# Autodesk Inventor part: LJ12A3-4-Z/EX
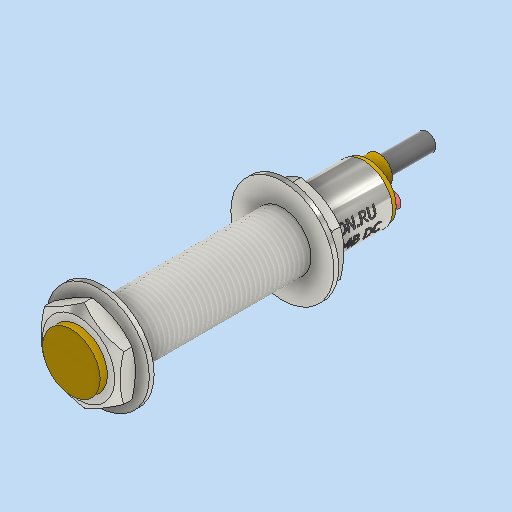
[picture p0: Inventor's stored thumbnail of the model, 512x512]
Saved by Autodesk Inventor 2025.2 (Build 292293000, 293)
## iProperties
Created: 2026-04
Part Number: LJ12A3-4-Z/EX
Material: Типовые
Description: D290-00327
Document SubType Name: Modeling
Designer: DN.RU
Mass: 50 g
Surface Area: 41.1858 cm^2
Volume: 8.64663 cm^3
Density: 5.78253 g/cm^3
Appearance: По умолчанию
Title: Концевой выключатель DN.ru
Author: DN.RU
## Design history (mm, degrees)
sketch "Эскиз1"
  geometry: C1 r 6 at (0, 0); 1 further point
  constraints: 1 centre point, 1 coincident
  dimensions: "d0" = 12 diameter of C1
extrude "Выдавливание1" new body sketch "Эскиз1" distance "d1" = 0.5; taper "d2" = 0 deg
sketch "Эскиз2"
  geometry: C1 r 6 at (0, 0); 1 further point
  constraints: 1 centre point, 1 coincident
  dimensions: "d3" = 12 diameter of C1
extrude "Выдавливание2" join sketch "Эскиз2" distance "d4" = 1; taper "d5" = 0 deg
sketch "Эскиз3"
  geometry: L1 (0, 0)-(8.25, 0); L2 (8.25, -4.763)-(0, -9.526); L3 (0, -9.526)-(-8.25, -4.763); L4 (-8.25, -4.763)-(-8.25, 4.763); L5 (-8.25, 4.763)-(0, 9.526); L6 (0, 9.526)-(8.25, 4.763); L7 (8.25, 4.763)-(8.25, -4.763); 1 further point
  constraints: 14 end point, 1 coincident, 1 horizontal, 1 midpoint, 13 other
  dimensions: "d6" = 8.25 distance of L1.start L1.end
extrude "Выдавливание3" join sketch "Эскиз3" distance "d7" = 4; taper "d8" = 0 deg
sketch "Эскиз4"
  geometry: C1 r 10.75 at (0, 0); 1 further point
  constraints: 1 centre point, 1 coincident
  dimensions: "d9" = 21.5 diameter of C1
extrude "Выдавливание4" join sketch "Эскиз4" distance "d10" = 1; taper "d11" = 0 deg
sketch "Эскиз5"
  geometry: C1 r 6 at (0, 0); 1 further point
  constraints: 1 centre point, 1 coincident
  dimensions: "d12" = 12 diameter of C1
extrude "Выдавливание5" join sketch "Эскиз5" distance "d13" = 37.5; taper "d14" = 0 deg
sketch "Эскиз6"
  geometry: C1 r 10.75 at (0, 0) reference; 1 further point
extrude "Выдавливание6" join sketch "Эскиз6" distance "d15" = 1; taper "d16" = 0 deg
sketch "Эскиз7"
  geometry: L1 (0, 9.526)-(-8.25, 4.763) reference; L2 (8.25, 4.763)-(0, 9.526) reference; L3 (8.25, -4.763)-(8.25, 4.763) reference; L4 (0, -9.526)-(8.25, -4.763) reference; L5 (-8.25, -4.763)-(0, -9.526) reference; L6 (-8.25, 4.763)-(-8.25, -4.763) reference; C1 r 6 at (0, 0) reference; 1 further point
extrude "Выдавливание7" join sketch "Эскиз7" distance "d17" = 4; taper "d18" = 0 deg
sketch "Эскиз9"
  geometry: C1 r 6 at (0, 0); 1 further point
  constraints: 1 centre point, 1 coincident
  dimensions: "d22" = 12 diameter of C1
extrude "Выдавливание9" join sketch "Эскиз9" distance "d23" = 12; taper "d24" = 0 deg
sketch "Эскиз10"
  geometry: C1 r 5.75 at (0, 0); 1 further point
  constraints: 1 centre point, 1 coincident
  dimensions: "d25" = 11.5 diameter of C1
extrude "Выдавливание10" join sketch "Эскиз10" distance "d26" = 1; taper "d27" = 0 deg
sketch "Эскиз11"
  geometry: C1 r 5.75 at (0, 0) reference; C2 r 1.559 at (-4.191, 0); 2 further points
  constraints: 1 centre point, 1 horizontal alignment, 3 other
extrude "Выдавливание11" join sketch "Эскиз11" distance "d29" = 1; taper "d30" = 0 deg
node "Непосредственное редактирование1"
sketch "Эскиз12"
  geometry: C1 r 2.875 at (0, 0) reference; C2 r 1.875 at (0, 0); 1 further point
  constraints: 1 centre point
  dimensions: "d34" = 1 radial gap between concentric circles of C1 C2
extrude "Выдавливание12" join sketch "Эскиз12" distance "d35" = 10; taper "d36" = 0 deg
feature "Резьба1" dims "d37" = 37.5, "d38" = 0
sketch "Эскиз13"
  geometry: L1 (6, 0.5)-(-6, 0.5) reference; L2 (0, 0.5)-(0, 6.956); L3 (9.526, -1)-(9.526, -5) reference; L4 (9.526, -3)-(12.26, -3); L5 (6, -6)-(6, -43.5) reference; L6 (6, -24.75)-(19.06, -24.75); L7 (9.526, -1)-(7.526, -1); L8 (4.763, -1)-(9.526, -1) reference; L9 (7.526, -1)-(9.897, -2.369); L10 (9.897, -2.369)-(9.897, -1); L11 (9.897, -1)-(9.526, -1); L12 (9.526, -5)-(7.526, -5); L13 (7.526, -5)-(9.897, -3.631); L14 (9.897, -3.631)-(9.897, -5); L15 (9.897, -5)-(9.526, -5); L16 (9.526, -48.5)-(7.526, -48.5); L17 (9.897, -48.5)-(9.526, -48.5); L18 (7.526, -48.5)-(9.897, -47.131); L19 (9.897, -47.131)-(9.897, -48.5); L20 (9.526, -48.5)-(9.526, -44.5); L21 (9.526, -44.5)-(7.526, -44.5); L22 (7.526, -44.5)-(9.897, -45.869); L23 (9.897, -45.869)-(9.897, -44.5); L24 (9.897, -44.5)-(9.526, -44.5); 3 further points
  constraints: 40 end point, 13 symmetric about line, 5 point on line, 3 midpoint, 2 horizontal, 2 perpendicular, 1 vertical
  dimensions: "d39" = 2 distance of L3.start L7.end; "d40" = 30 deg angle of L9 L7
revolve "Вращение1" sketch "Эскиз13" stored, may be unused: angle "d41" = 90 deg
node "РабПлоскость1"
sketch "Эскиз14"
  geometry: L1 (2.618, -0.69)-(2.618, -16.362); L2 (2.618, -16.362)-(-5.513, -16.362); L3 (-5.513, -16.362)-(-5.513, -0.69); L4 (-5.513, -0.69)-(2.618, -0.69); 1 further point
  constraints: 2 other
feature "Рельеф1" sketch "Эскиз14" dims "d9" = 21.5, "d42" = 0.1, "d43" = 0
node "Твердое тело1"
node "Спроецированная петля1"
node "Спроецированная петля2"
feature "Перенос1" dims "d33" = 4
other parameters: "d31" = 0, "d32" = 0
